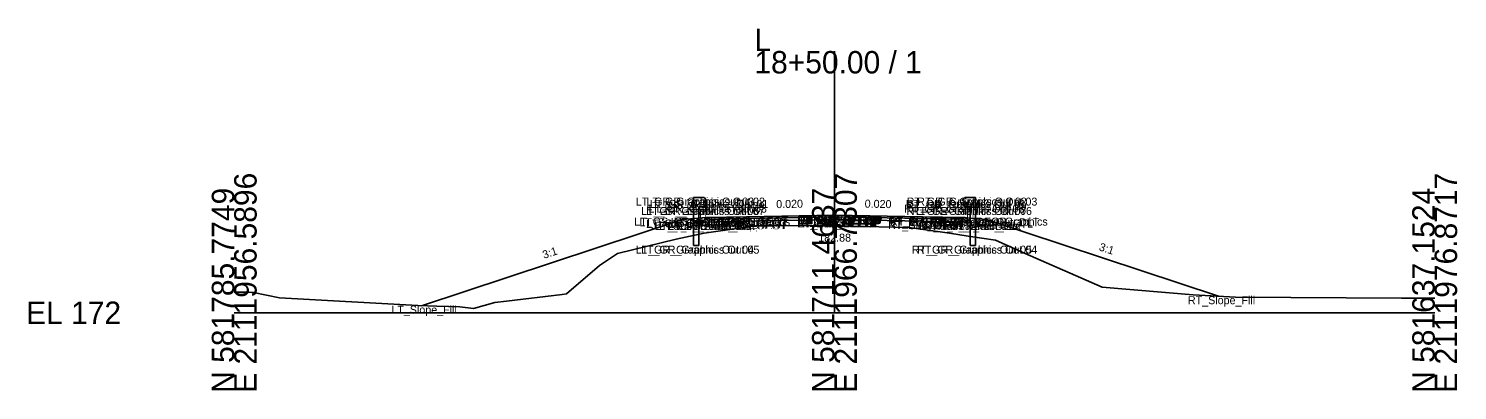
# Model space of a CAD drawing. Extents: x -26 to 3453, y -333 to 9539.
# Drawn here: x -25.7 to 152.8, y 8990.3 to 9035.5 of the extents above; entities that cross this region are included whole.
import ezdxf

# ---------------------------------------------------------------- set-up
doc = ezdxf.new("R2010")
doc.units = 0
for name, color, linetype in [('Default', 7, 'Continuous'), ('Exist Cross Section Cell', 7, 'Continuous'), ('Exist XS Center Line Elevation Label', 7, 'Continuous'), ('Exist XS Ground Line', 7, 'Continuous'), ('Prop CMT Guardrail Graphics', 7, 'Continuous'), ('Prop CMT Pvmt Course 1', 7, 'Continuous'), ('Prop CMT Pvmt Course 2', 7, 'Continuous'), ('Prop CMT Pvmt Course 3', 7, 'Continuous'), ('Prop CMT Pvmt Surface', 7, 'Continuous'), ('Prop CMT Pvmt Surface Shoulder', 7, 'Continuous'), ('Prop CMT Shld Paved Course 1', 7, 'Continuous'), ('Prop CMT Shld Paved Course 2', 7, 'Continuous'), ('Prop CMT Shld Paved Course 3', 7, 'Continuous'), ('Prop CMT Slope Grass', 7, 'Continuous'), ('Prop CMT Subgrade Earthwork', 7, 'Continuous'), ('Prop XS SE Text', 7, 'Continuous'), ('Prop XS Side Slope Text', 7, 'Continuous'), ('Scratch_Level_0', 7, 'Continuous')]:
    doc.layers.add(name, color=color, linetype=linetype)

msp = doc.modelspace()

# ---------------------------------------------------------------- linework, layer by layer
at = {"layer": 'Exist Cross Section Cell'}
for p, q in [((75, 9000), (75, 9032.68)), ((0, 9000), (75, 9000)), ((75, 9000), (150, 9000))]:
    msp.add_line(p, q, dxfattribs=at)
at = {"layer": 'Exist XS Ground Line'}
for p, q in [((58.73, 9009.95), (65.14, 9010.85)), ((65.14, 9010.85), (67.36, 9010.86)), ((67.36, 9010.86), (74.38, 9010.89)), ((74.38, 9010.89), (75, 9010.88)), ((75, 9010.88), (76.81, 9010.83)), ((76.81, 9010.83), (84.35, 9010.63)), ((84.35, 9010.63), (89.39, 9009.95)), ((47.89, 9007.42), (55.23, 9009.19)), ((55.23, 9009.19), (58.73, 9009.95)), ((89.39, 9009.95), (91.7, 9009.57)), ((91.7, 9009.57), (95.14, 9009.06)), ((95.14, 9009.06), (98.85, 9007.41)), ((45.65, 9005.9), (47.89, 9007.42)), ((98.85, 9007.41), (108.45, 9003.2)), ((41.52, 9002.36), (45.65, 9005.9)), ((0, 9002.57), (1.88, 9002.58)), ((1.88, 9002.58), (2.43, 9002.54)), ((2.43, 9002.54), (5.65, 9001.85)), ((5.65, 9001.85), (22.94, 9000.9)), ((34.01, 9001.45), (40.96, 9002.28)), ((40.96, 9002.28), (41.52, 9002.36)), ((108.45, 9003.2), (119.82, 9002.25)), ((119.82, 9002.25), (125.11, 9001.96)), ((125.11, 9001.96), (145.86, 9001.84)), ((145.86, 9001.84), (150, 9001.82)), ((22.94, 9000.9), (25.3, 9000.83)), ((25.3, 9000.83), (28.21, 9000.76)), ((28.21, 9000.76), (29.89, 9000.52)), ((29.89, 9000.52), (32.58, 9001.27)), ((32.58, 9001.27), (34.01, 9001.45))]:
    msp.add_line(p, q, dxfattribs=at)
at = {"layer": 'Prop CMT Guardrail Graphics'}
for points in [[(57.39, 9008.38), (57.39, 9014.38)], [(57.39, 9014.38), (58.72, 9014.38), (58.99, 9014.09)], [(92.61, 9014.38), (91.28, 9014.38), (91.01, 9014.09)], [(92.61, 9008.38), (92.61, 9014.38)], [(58.99, 9013.51), (58.72, 9013.21), (58.05, 9013.21)], [(58.05, 9013.21), (58.05, 9008.38)], [(58.99, 9014.09), (58.72, 9013.8)], [(58.72, 9013.8), (58.99, 9013.51)], [(91.01, 9014.09), (91.28, 9013.8)], [(91.28, 9013.8), (91.01, 9013.51)], [(91.01, 9013.51), (91.28, 9013.21), (91.95, 9013.21)], [(91.95, 9013.21), (91.95, 9008.38)], [(58.05, 9008.38), (57.39, 9008.38)], [(91.95, 9008.38), (92.61, 9008.38)]]:
    msp.add_lwpolyline(points, dxfattribs=at)
at = {"layer": 'Prop CMT Pvmt Course 1'}
for points in [[(75, 9012.2), (64, 9011.98)], [(64, 9011.77), (75, 9011.99)], [(64, 9011.98), (64, 9011.77)], [(75, 9011.99), (75, 9012.2)], [(75, 9012.2), (86, 9011.98)], [(75, 9011.99), (75, 9012.2)], [(86, 9011.77), (75, 9011.99)], [(86, 9011.98), (86, 9011.77)]]:
    msp.add_lwpolyline(points, dxfattribs=at)
msp.add_lwpolyline([(75, 9011.99), (75, 9012.08), (75, 9012.08), (75, 9011.99)], close=True, dxfattribs=at)
msp.add_lwpolyline([(75, 9011.99), (75, 9012.08), (75, 9012.08), (75, 9011.99)], close=True, dxfattribs=at)
at = {"layer": 'Prop CMT Pvmt Course 2'}
for points in [[(75, 9011.99), (64, 9011.77)], [(64, 9011.77), (64, 9011.44)], [(64, 9011.44), (75, 9011.66)], [(75, 9011.66), (75, 9011.99)], [(75, 9011.66), (75, 9011.99)], [(75, 9011.99), (86, 9011.77)], [(86, 9011.44), (75, 9011.66)], [(86, 9011.77), (86, 9011.44)]]:
    msp.add_lwpolyline(points, dxfattribs=at)
at = {"layer": 'Prop CMT Pvmt Course 3'}
for points in [[(75, 9011.66), (64, 9011.44)], [(64, 9011.44), (75, 9011.66)], [(64, 9011.44), (64, 9011.44)], [(75, 9011.66), (75, 9011.66)], [(75, 9011.66), (86, 9011.44)], [(86, 9011.44), (75, 9011.66)], [(75, 9011.66), (75, 9011.66)], [(86, 9011.44), (86, 9011.44)]]:
    msp.add_lwpolyline(points, dxfattribs=at)
at = {"layer": 'Prop CMT Pvmt Surface'}
for points in [[(75, 9012.2), (64, 9011.98)], [(75, 9012.2), (86, 9011.98)]]:
    msp.add_lwpolyline(points, dxfattribs=at)
at = {"layer": 'Prop CMT Pvmt Surface Shoulder'}
for points in [[(64, 9011.98), (59, 9011.88)], [(86, 9011.98), (91, 9011.88)]]:
    msp.add_lwpolyline(points, dxfattribs=at)
at = {"layer": 'Prop CMT Shld Paved Course 1'}
for points in [[(64, 9011.98), (59, 9011.88), (58.79, 9011.67)], [(58.79, 9011.67), (64, 9011.77)], [(64, 9011.77), (64, 9011.98)], [(86, 9011.98), (91, 9011.88), (91.21, 9011.67)], [(86, 9011.77), (86, 9011.98)], [(91.21, 9011.67), (86, 9011.77)]]:
    msp.add_lwpolyline(points, dxfattribs=at)
at = {"layer": 'Prop CMT Shld Paved Course 2'}
for points in [[(64, 9011.77), (58.79, 9011.67), (58.45, 9011.33)], [(58.45, 9011.33), (64, 9011.44)], [(64, 9011.44), (64, 9011.77)], [(86, 9011.77), (91.21, 9011.67), (91.55, 9011.33)], [(86, 9011.44), (86, 9011.77)], [(91.55, 9011.33), (86, 9011.44)]]:
    msp.add_lwpolyline(points, dxfattribs=at)
at = {"layer": 'Prop CMT Shld Paved Course 3'}
for points in [[(64, 9011.44), (58.45, 9011.33)], [(58.45, 9011.33), (64, 9011.44)], [(58.45, 9011.33), (58.45, 9011.33), (58.45, 9011.33)], [(64, 9011.44), (64, 9011.44)], [(86, 9011.44), (91.55, 9011.33)], [(91.55, 9011.33), (86, 9011.44)], [(86, 9011.44), (86, 9011.44)], [(91.55, 9011.33), (91.55, 9011.33), (91.55, 9011.33)]]:
    msp.add_lwpolyline(points, dxfattribs=at)
at = {"layer": 'Prop CMT Slope Grass'}
for points in [[(56, 9011.64), (23.4, 9000.88)], [(58.99, 9011.88), (56, 9011.64)], [(59, 9011.88), (58.99, 9011.88)], [(91, 9011.88), (91.01, 9011.88)], [(91.01, 9011.88), (94, 9011.64)], [(94, 9011.64), (122.99, 9002.07)]]:
    msp.add_lwpolyline(points, dxfattribs=at)
at = {"layer": 'Prop CMT Subgrade Earthwork'}
for points in [[(58.45, 9011.33), (57.98, 9011.8)], [(64, 9011.44), (58.45, 9011.33)], [(75, 9011.66), (64, 9011.44)], [(75, 9011.66), (86, 9011.44)], [(86, 9011.44), (91.55, 9011.33)], [(91.55, 9011.33), (92.02, 9011.8)]]:
    msp.add_lwpolyline(points, dxfattribs=at)

# ---------------------------------------------------------------- texts
at = {"layer": 'Default'}
msp.add_text('-', height=0.0001, dxfattribs=at).set_placement((0, 9000))
at = {"layer": 'Exist Cross Section Cell'}
for s, p in [('L', (65, 9032.68)), ('18+50.00 / 1', (65, 9029.88)), ('EL 172', (-26, 8998.6))]:
    msp.add_text(s, height=2.8, dxfattribs=at).set_placement(p)
for s, p in [('E 2111956.5896', (2.8, 8990)), ('E 2111966.7307', (77.8, 8990)), ('E 2111976.8717', (152.8, 8990)), ('N 581785.7749', (0, 8990)), ('N 581711.4637', (75, 8990)), ('N 581637.1524', (150, 8990))]:
    msp.add_text(s, height=2.8, rotation=90, dxfattribs=at).set_placement(p)
at = {"layer": 'Exist XS Center Line Elevation Label'}
msp.add_text('182.88', height=1, dxfattribs=at).set_placement((72.98, 9008.88))
at = {"layer": 'Prop XS SE Text'}
for rotation, p in [(1.1458, (67.73, 9013.06)), (358.8542, (78.77, 9013.13))]:
    msp.add_text('0.020', height=1, rotation=rotation, dxfattribs=at).set_placement(p)
at = {"layer": 'Prop XS Side Slope Text'}
for rotation, p in [(18.2629, (38.71, 9006.73)), (341.7371, (107.98, 9007.82))]:
    msp.add_text('3:1', height=1, rotation=rotation, dxfattribs=at).set_placement(p)
at = {"layer": 'Scratch_Level_0'}
for s, p in [('LT_GR_Graphics Out 03', (50.17, 9013.38)), ('LT_GR_Graphics Out 02', (51.52, 9013.38)), ('LT_GR_Graphics Out 01', (51.94, 9013.09)), ('RT_GR_Graphics Out 01', (83.9, 9013.09)), ('RT_GR_Graphics Out 02', (84.02, 9013.38)), ('RT_GR_Graphics Out 03', (85.34, 9013.38)), ('LT_GR_Graphics Out 06', (50.83, 9012.21)), ('LT_GR_Graphics Out 07', (51.48, 9012.21)), ('LT_GR_Graphics Out 09', (51.49, 9012.8)), ('LT_GR_Graphics Out 08', (51.76, 9012.51)), ('RT_GR_Graphics Out 08', (83.72, 9012.51)), ('RT_GR_Graphics Out 07', (83.98, 9012.21)), ('RT_GR_Graphics Out 09', (84, 9012.8)), ('RT_GR_Graphics Out 06', (84.66, 9012.21)), ('LT_GS_OS_GR_Face_Graphics', (49.99, 9010.88)), ('LT_Sub_Trench_Out_DLT', (50.63, 9010.8)), ('LT_GS_OS_CTL', (51.46, 9010.64)), ('LT_Sub_Trench_Out', (52.56, 9010.33)), ('LT_PS3_Shelf_Out', (53.1, 9010.33)), ('LT_PS3_OEOP', (54.23, 9010.33)), ('LT_PS2_OEOP', (54.57, 9010.67)), ('LT_PS1_OEOP', (54.91, 9010.88)), ('LT_PV2_OEOT', (59.75, 9010.77)), ('LT_PV3_OEOT', (59.75, 9010.44)), ('LT_Sub_OEOT', (59.77, 9010.44)), ('LT_PV1_OEOT', (59.87, 9010.98)), ('RT_PV2_OEEOP', (70.33, 9010.99)), ('RT_PV3_OEEOP', (70.33, 9010.66)), ('RT_Sub_OEEOP', (70.36, 9010.66)), ('LT_PV2_OEEOP', (70.39, 9010.99)), ('LT_PV3_OEEOP', (70.39, 9010.66)), ('LT_Sub_OEEOP', (70.42, 9010.66)), ('RT_PV1_OEEOP', (70.45, 9011.08)), ('LT_PV1_OEEOP', (70.51, 9011.08)), ('RT_PV2_IEEOP', (70.71, 9010.99)), ('LT_PV2_IEEOP', (70.77, 9010.99)), ('RT_PV1_IEEOP', (70.83, 9011.08)), ('LT_PV1_IEEOP', (70.89, 9011.08)), ('PV2_PGL', (72.35, 9010.99)), ('PV1_PGL', (72.47, 9011.2)), ('RT_PV2_OEOT', (81.69, 9010.77)), ('RT_PV3_OEOT', (81.69, 9010.44)), ('RT_Sub_OEOT', (81.71, 9010.44)), ('RT_PV1_OEOT', (81.81, 9010.98)), ('RT_GS_OS_GR_Face_Graphics', (81.95, 9010.88)), ('RT_Sub_Trench_Out_DLT', (84.61, 9010.8)), ('RT_Sub_Trench_Out', (85.6, 9010.33)), ('RT_PS3_Shelf_Out', (86.15, 9010.33)), ('RT_PS1_OEOP', (86.85, 9010.88)), ('RT_PS2_OEOP', (86.94, 9010.67)), ('RT_PS3_OEOP', (87.28, 9010.33)), ('RT_GS_OS_CTL', (89.4, 9010.64)), ('LT_GR_Graphics Out 04', (50.16, 9007.38)), ('LT_GR_Graphics Out 05', (50.83, 9007.38)), ('RT_GR_Graphics Out 05', (84.67, 9007.38)), ('RT_GR_Graphics Out 04', (85.32, 9007.38)), ('RT_Slope_Fill', (119.17, 9001.07)), ('LT_Slope_Fill', (19.64, 8999.88))]:
    msp.add_text(s, height=1, dxfattribs=at).set_placement(p)

doc.saveas('drawing.dxf')
